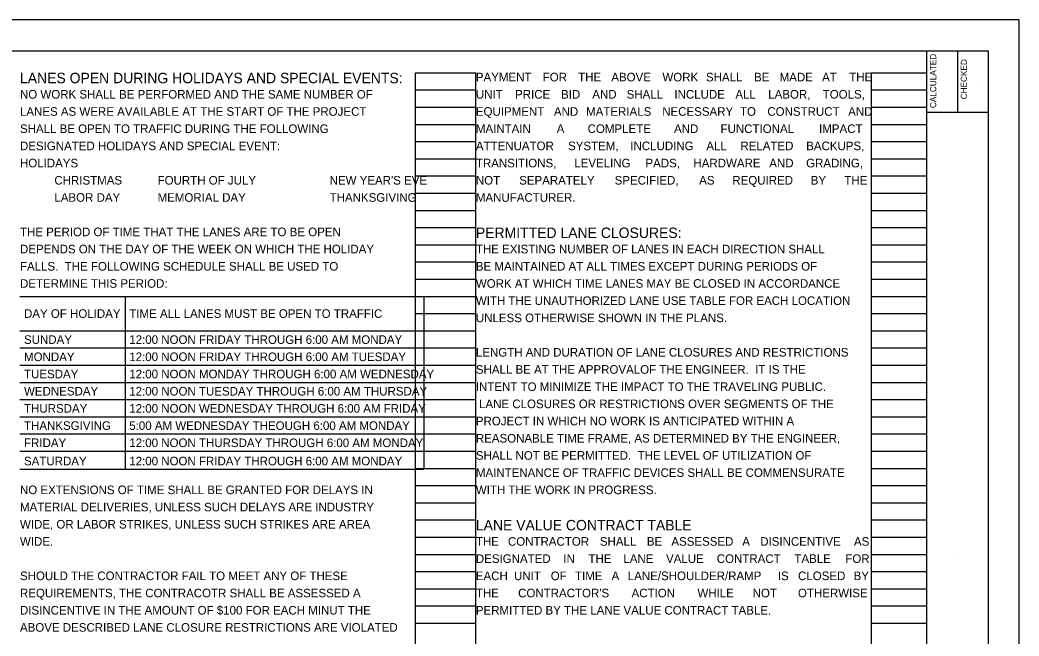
# Model space of a CAD drawing. Extents: x 0 to 34, y 0 to 22.
# Drawn here: x 17.74 to 34, y 11.97 to 22 of the extents above; entities that cross this region are included whole.
import ezdxf

# ---------------------------------------------------------------- set-up
doc = ezdxf.new("R2010")
doc.units = 0
for name, color, linetype in [('BD_P_Text', 7, 'Continuous'), ('SH_Border', 7, 'Continuous'), ('SH_Cut_Line', 7, 'Continuous'), ('SH_Data', 7, 'Continuous'), ('SH_Text', 7, 'Continuous')]:
    doc.layers.add(name, color=color, linetype=linetype)

msp = doc.modelspace()

# ---------------------------------------------------------------- linework, layer by layer
at = {"layer": 'SH_Border'}
for p, q in [((32.5, 0.5), (32.5, 21.5)), ((33, 21.5), (33, 20.5)), ((32.5, 20.5), (33.5, 20.5))]:
    msp.add_line(p, q, dxfattribs=at)
msp.add_lwpolyline([(2, 21.5), (33.5, 21.5), (33.5, 0.5), (2, 0.5)], close=True, dxfattribs=at)
at = {"layer": 'SH_Cut_Line'}
msp.add_lwpolyline([(0, 0), (34, 0), (34, 22), (0, 22)], close=True, dxfattribs=at)
at = {"layer": 'SH_Data'}
for p, q in [((24.18, 0.98), (24.18, 21.14)), ((24.18, 21.14), (25.16, 21.14)), ((25.16, 0.98), (25.16, 21.14)), ((31.6, 0.98), (31.6, 21.14)), ((31.6, 21.14), (32.5, 21.14)), ((32.5, 0.98), (32.5, 21.14)), ((32.92, 21.004), (32.92, 21.004)), ((33.42, 21.004), (33.42, 21.004)), ((24.18, 20.86), (25.16, 20.86)), ((31.6, 20.86), (32.5, 20.86)), ((24.18, 20.58), (25.16, 20.58)), ((31.6, 20.58), (32.5, 20.58)), ((24.18, 20.3), (25.16, 20.3)), ((31.6, 20.3), (32.5, 20.3)), ((24.18, 20.02), (25.16, 20.02)), ((31.6, 20.02), (32.5, 20.02)), ((24.18, 19.74), (25.16, 19.74)), ((31.6, 19.74), (32.5, 19.74)), ((24.18, 19.46), (25.16, 19.46)), ((31.6, 19.46), (32.5, 19.46)), ((24.18, 19.18), (25.16, 19.18)), ((31.6, 19.18), (32.5, 19.18)), ((24.18, 18.9), (25.16, 18.9)), ((31.6, 18.9), (32.5, 18.9)), ((24.18, 18.62), (25.16, 18.62)), ((31.6, 18.62), (32.5, 18.62)), ((24.18, 18.34), (25.16, 18.34)), ((31.6, 18.34), (32.5, 18.34)), ((24.18, 18.06), (25.16, 18.06)), ((31.6, 18.06), (32.5, 18.06)), ((24.18, 17.78), (25.16, 17.78)), ((31.6, 17.78), (32.5, 17.78)), ((17.74, 17.5), (24.312, 17.5)), ((19.453, 17.5), (19.453, 14.684)), ((24.18, 17.5), (25.16, 17.5)), ((24.312, 17.5), (24.312, 14.684)), ((31.6, 17.5), (32.5, 17.5)), ((24.18, 17.22), (25.16, 17.22)), ((31.6, 17.22), (32.5, 17.22)), ((17.74, 16.94), (24.312, 16.94)), ((24.18, 16.94), (25.16, 16.94)), ((31.6, 16.94), (32.5, 16.94)), ((17.74, 16.66), (24.312, 16.66)), ((24.18, 16.66), (25.16, 16.66)), ((31.6, 16.66), (32.5, 16.66)), ((17.74, 16.38), (24.312, 16.38)), ((24.18, 16.38), (25.16, 16.38)), ((31.6, 16.38), (32.5, 16.38)), ((17.74, 16.1), (24.312, 16.1)), ((24.18, 16.1), (25.16, 16.1)), ((31.6, 16.1), (32.5, 16.1)), ((17.74, 15.82), (24.312, 15.82)), ((24.18, 15.82), (25.16, 15.82)), ((31.6, 15.82), (32.5, 15.82)), ((17.74, 15.54), (24.312, 15.54)), ((24.18, 15.54), (25.16, 15.54)), ((31.6, 15.54), (32.5, 15.54)), ((17.74, 15.26), (24.312, 15.26)), ((24.18, 15.26), (25.16, 15.26)), ((31.6, 15.26), (32.5, 15.26)), ((17.74, 14.98), (24.312, 14.98)), ((24.18, 14.98), (25.16, 14.98)), ((31.6, 14.98), (32.5, 14.98)), ((17.74, 14.684), (24.312, 14.684)), ((24.18, 14.7), (25.16, 14.7)), ((31.6, 14.7), (32.5, 14.7)), ((24.18, 14.42), (25.16, 14.42)), ((31.6, 14.42), (32.5, 14.42)), ((24.18, 14.14), (25.16, 14.14)), ((31.6, 14.14), (32.5, 14.14)), ((24.18, 13.86), (25.16, 13.86)), ((31.6, 13.86), (32.5, 13.86)), ((24.18, 13.58), (25.16, 13.58)), ((31.6, 13.58), (32.5, 13.58)), ((24.18, 13.3), (25.16, 13.3)), ((31.6, 13.3), (32.5, 13.3)), ((33, 13.292), (33, 13.292)), ((24.18, 13.02), (25.16, 13.02)), ((31.6, 13.02), (32.5, 13.02)), ((24.18, 12.74), (25.16, 12.74)), ((31.6, 12.74), (32.5, 12.74)), ((24.18, 12.46), (25.16, 12.46)), ((31.6, 12.46), (32.5, 12.46)), ((24.18, 12.18), (25.16, 12.18)), ((31.6, 12.18), (32.5, 12.18))]:
    msp.add_line(p, q, dxfattribs=at)

# ---------------------------------------------------------------- texts
at = {"layer": 'BD_P_Text'}
for s, height, p in [('LANES OPEN DURING HOLIDAYS AND SPECIAL EVENTS:', 0.17, (17.74, 20.97)), ('PAYMENT ', 0.14, (25.16, 21)), ('FOR ', 0.14, (26.248, 21)), ('THE ', 0.14, (26.825, 21)), ('ABOVE ', 0.14, (27.364, 21)), ('WORK ', 0.14, (28.196, 21)), ('SHALL ', 0.14, (28.905, 21)), ('BE ', 0.14, (29.688, 21)), ('MADE ', 0.14, (30.104, 21)), ('AT ', 0.14, (30.795, 21)), ('THE ', 0.14, (31.236, 21)), ('NO WORK SHALL BE PERFORMED AND THE SAME NUMBER OF ', 0.14, (17.74, 20.72)), ('UNIT ', 0.14, (25.16, 20.72)), ('PRICE ', 0.14, (25.798, 20.72)), ('BID ', 0.14, (26.546, 20.72)), ('AND ', 0.14, (27.055, 20.72)), ('SHALL ', 0.14, (27.613, 20.72)), ('INCLUDE ', 0.14, (28.391, 20.72)), ('ALL ', 0.14, (29.384, 20.72)), ('LABOR, ', 0.14, (29.918, 20.72)), ('TOOLS, ', 0.14, (30.805, 20.72)), ('LANES AS WERE AVAILABLE AT THE START OF THE PROJECT ', 0.14, (17.74, 20.44)), ('EQUIPMENT ', 0.14, (25.16, 20.44)), ('AND ', 0.14, (26.43, 20.44)), ('MATERIALS ', 0.14, (26.954, 20.44)), ('NECESSARY ', 0.14, (28.193, 20.44)), ('TO ', 0.14, (29.458, 20.44)), ('CONSTRUCT ', 0.14, (29.904, 20.44)), ('AND ', 0.14, (31.22, 20.44)), ('SHALL BE OPEN TO TRAFFIC DURING THE FOLLOWING ', 0.14, (17.74, 20.16)), ('MAINTAIN ', 0.14, (25.16, 20.16)), ('A ', 0.14, (26.476, 20.16)), ('COMPLETE ', 0.14, (26.979, 20.16)), ('AND ', 0.14, (28.385, 20.16)), ('FUNCTIONAL ', 0.14, (29.142, 20.16)), ('IMPACT ', 0.14, (30.746, 20.16)), ('DESIGNATED HOLIDAYS AND SPECIAL EVENT:', 0.14, (17.74, 19.88)), ('ATTENUATOR ', 0.14, (25.16, 19.88)), ('SYSTEM, ', 0.14, (26.661, 19.88)), ('INCLUDING ', 0.14, (27.674, 19.88)), ('ALL ', 0.14, (28.911, 19.88)), ('RELATED ', 0.14, (29.465, 19.88)), ('BACKUPS, ', 0.14, (30.536, 19.88)), ('HOLIDAYS', 0.14, (17.74, 19.6)), ('TRANSITIONS, ', 0.14, (25.16, 19.6)), ('LEVELING ', 0.14, (26.761, 19.6)), ('PADS, ', 0.14, (27.92, 19.6)), ('HARDWARE ', 0.14, (28.701, 19.6)), ('AND ', 0.14, (29.935, 19.6)), ('GRADING, ', 0.14, (30.535, 19.6)), ('CHRISTMAS', 0.14, (18.3, 19.32)), ('FOURTH OF JULY', 0.14, (19.98, 19.32)), ("NEW YEAR'S EVE", 0.14, (22.78, 19.32)), ('NOT ', 0.14, (25.16, 19.32)), ('SEPARATELY ', 0.14, (25.865, 19.32)), ('SPECIFIED, ', 0.14, (27.419, 19.32)), ('AS ', 0.14, (28.794, 19.32)), ('REQUIRED ', 0.14, (29.334, 19.32)), ('BY ', 0.14, (30.61, 19.32)), ('THE ', 0.14, (31.157, 19.32)), ('LABOR DAY', 0.14, (18.3, 19.04)), ('MEMORIAL DAY ', 0.14, (19.98, 19.04)), ('THANKSGIVING', 0.14, (22.78, 19.04)), ('MANUFACTURER.', 0.14, (25.16, 19.04)), ('THE PERIOD OF TIME THAT THE LANES ARE TO BE OPEN ', 0.14, (17.74, 18.48)), ('PERMITTED LANE CLOSURES:', 0.17, (25.16, 18.45)), ('DEPENDS ON THE DAY OF THE WEEK ON WHICH THE HOLIDAY ', 0.14, (17.74, 18.2)), ('THE EXISTING NUMBER OF LANES IN EACH DIRECTION SHALL ', 0.14, (25.16, 18.2)), ('FALLS.  THE FOLLOWING SCHEDULE SHALL BE USED TO ', 0.14, (17.74, 17.92)), ('BE MAINTAINED AT ALL TIMES EXCEPT DURING PERIODS OF ', 0.14, (25.16, 17.92)), ('DETERMINE THIS PERIOD:', 0.14, (17.74, 17.64)), ('WORK AT WHICH TIME LANES MAY BE CLOSED IN ACCORDANCE ', 0.14, (25.16, 17.64)), ('WITH THE UNAUTHORIZED LANE USE TABLE FOR EACH LOCATION ', 0.14, (25.16, 17.36)), ('UNLESS OTHERWISE SHOWN IN THE PLANS.', 0.14, (25.16, 17.08)), ('LENGTH AND DURATION OF LANE CLOSURES AND RESTRICTIONS ', 0.14, (25.16, 16.52)), ('SHALL BE AT THE APPROVALOF THE ENGINEER.  IT IS THE ', 0.14, (25.16, 16.24)), ('INTENT TO MINIMIZE THE IMPACT TO THE TRAVELING PUBLIC. ', 0.14, (25.16, 15.96)), (' LANE CLOSURES OR RESTRICTIONS OVER SEGMENTS OF THE ', 0.14, (25.16, 15.68)), ('PROJECT IN WHICH NO WORK IS ANTICIPATED WITHIN A ', 0.14, (25.16, 15.4)), ('REASONABLE TIME FRAME, AS DETERMINED BY THE ENGINEER, ', 0.14, (25.16, 15.12)), ('SHALL NOT BE PERMITTED.  THE LEVEL OF UTILIZATION OF ', 0.14, (25.16, 14.84)), ('MAINTENANCE OF TRAFFIC DEVICES SHALL BE COMMENSURATE ', 0.14, (25.16, 14.56)), ('NO EXTENSIONS OF TIME SHALL BE GRANTED FOR DELAYS IN ', 0.14, (17.74, 14.28)), ('WITH THE WORK IN PROGRESS.', 0.14, (25.16, 14.28)), ('MATERIAL DELIVERIES, UNLESS SUCH DELAYS ARE INDUSTRY ', 0.14, (17.74, 14)), ('WIDE, OR LABOR STRIKES, UNLESS SUCH STRIKES ARE AREA ', 0.14, (17.74, 13.72)), ('LANE VALUE CONTRACT TABLE', 0.17, (25.16, 13.69)), ('WIDE.', 0.14, (17.74, 13.44)), ('THE ', 0.14, (25.16, 13.44)), ('CONTRACTOR ', 0.14, (25.682, 13.44)), ('SHALL ', 0.14, (27.178, 13.44)), ('BE ', 0.14, (27.943, 13.44)), ('ASSESSED ', 0.14, (28.342, 13.44)), ('A ', 0.14, (29.496, 13.44)), ('DISINCENTIVE ', 0.14, (29.788, 13.44)), ('AS ', 0.14, (31.313, 13.44)), ('DESIGNATED ', 0.14, (25.16, 13.16)), ('IN ', 0.14, (26.584, 13.16)), ('THE ', 0.14, (26.993, 13.16)), ('LANE ', 0.14, (27.561, 13.16)), ('VALUE ', 0.14, (28.255, 13.16)), ('CONTRACT ', 0.14, (29.081, 13.16)), ('TABLE ', 0.14, (30.345, 13.16)), ('FOR ', 0.14, (31.173, 13.16)), ('SHOULD THE CONTRACTOR FAIL TO MEET ANY OF THESE ', 0.14, (17.74, 12.88)), ('EACH ', 0.14, (25.16, 12.88)), ('UNIT ', 0.14, (25.781, 12.88)), ('OF ', 0.14, (26.379, 12.88)), ('TIME ', 0.14, (26.774, 12.88)), ('A ', 0.14, (27.369, 12.88)), ('LANE/SHOULDER/RAMP ', 0.14, (27.633, 12.88)), ('IS ', 0.14, (30.075, 12.88)), ('CLOSED ', 0.14, (30.404, 12.88)), ('BY ', 0.14, (31.308, 12.88)), ('REQUIREMENTS, THE CONTRACOTR SHALL BE ASSESSED A ', 0.14, (17.74, 12.6)), ('THE ', 0.14, (25.16, 12.6)), ("CONTRACTOR'S ", 0.14, (25.848, 12.6)), ('ACTION ', 0.14, (27.694, 12.6)), ('WHILE ', 0.14, (28.766, 12.6)), ('NOT ', 0.14, (29.664, 12.6)), ('OTHERWISE ', 0.14, (30.402, 12.6)), ('DISINCENTIVE IN THE AMOUNT OF $100 FOR EACH MINUT THE ', 0.14, (17.74, 12.32)), ('PERMITTED BY THE LANE VALUE CONTRACT TABLE.', 0.14, (25.16, 12.32)), ('ABOVE DESCRIBED LANE CLOSURE RESTRICTIONS ARE VIOLATED ', 0.14, (17.74, 12.04))]:
    msp.add_text(s, height=height, dxfattribs=at).set_placement(p)
at = {"layer": 'SH_Data'}
for s, p in [('CALCULATED', (32.652, 20.565)), ('CHECKED', (33.152, 20.708))]:
    msp.add_text(s, height=0.1, rotation=90, dxfattribs=at).set_placement(p)
at = {"layer": 'SH_Text'}
for s, p in [('DAY OF HOLIDAY', (17.806, 17.15)), ('TIME ALL LANES MUST BE OPEN TO TRAFFIC', (19.519, 17.15)), ('SUNDAY', (17.806, 16.726)), ('12:00 NOON FRIDAY THROUGH 6:00 AM MONDAY', (19.519, 16.726)), ('MONDAY', (17.806, 16.446)), ('12:00 NOON FRIDAY THROUGH 6:00 AM TUESDAY', (19.519, 16.446)), ('TUESDAY', (17.806, 16.166)), ('12:00 NOON MONDAY THROUGH 6:00 AM WEDNESDAY', (19.519, 16.166)), ('WEDNESDAY', (17.806, 15.886)), ('12:00 NOON TUESDAY THROUGH 6:00 AM THURSDAY', (19.519, 15.886)), ('THURSDAY', (17.806, 15.606)), ('12:00 NOON WEDNESDAY THROUGH 6:00 AM FRIDAY', (19.519, 15.606)), ('THANKSGIVING', (17.806, 15.326)), ('5:00 AM WEDNESDAY THEOUGH 6:00 AM MONDAY', (19.519, 15.326)), ('FRIDAY', (17.806, 15.046)), ('12:00 NOON THURSDAY THROUGH 6:00 AM MONDAY', (19.519, 15.046)), ('SATURDAY', (17.806, 14.749)), ('12:00 NOON FRIDAY THROUGH 6:00 AM MONDAY', (19.519, 14.749))]:
    msp.add_text(s, height=0.14, dxfattribs=at).set_placement(p)

doc.saveas('drawing.dxf')
